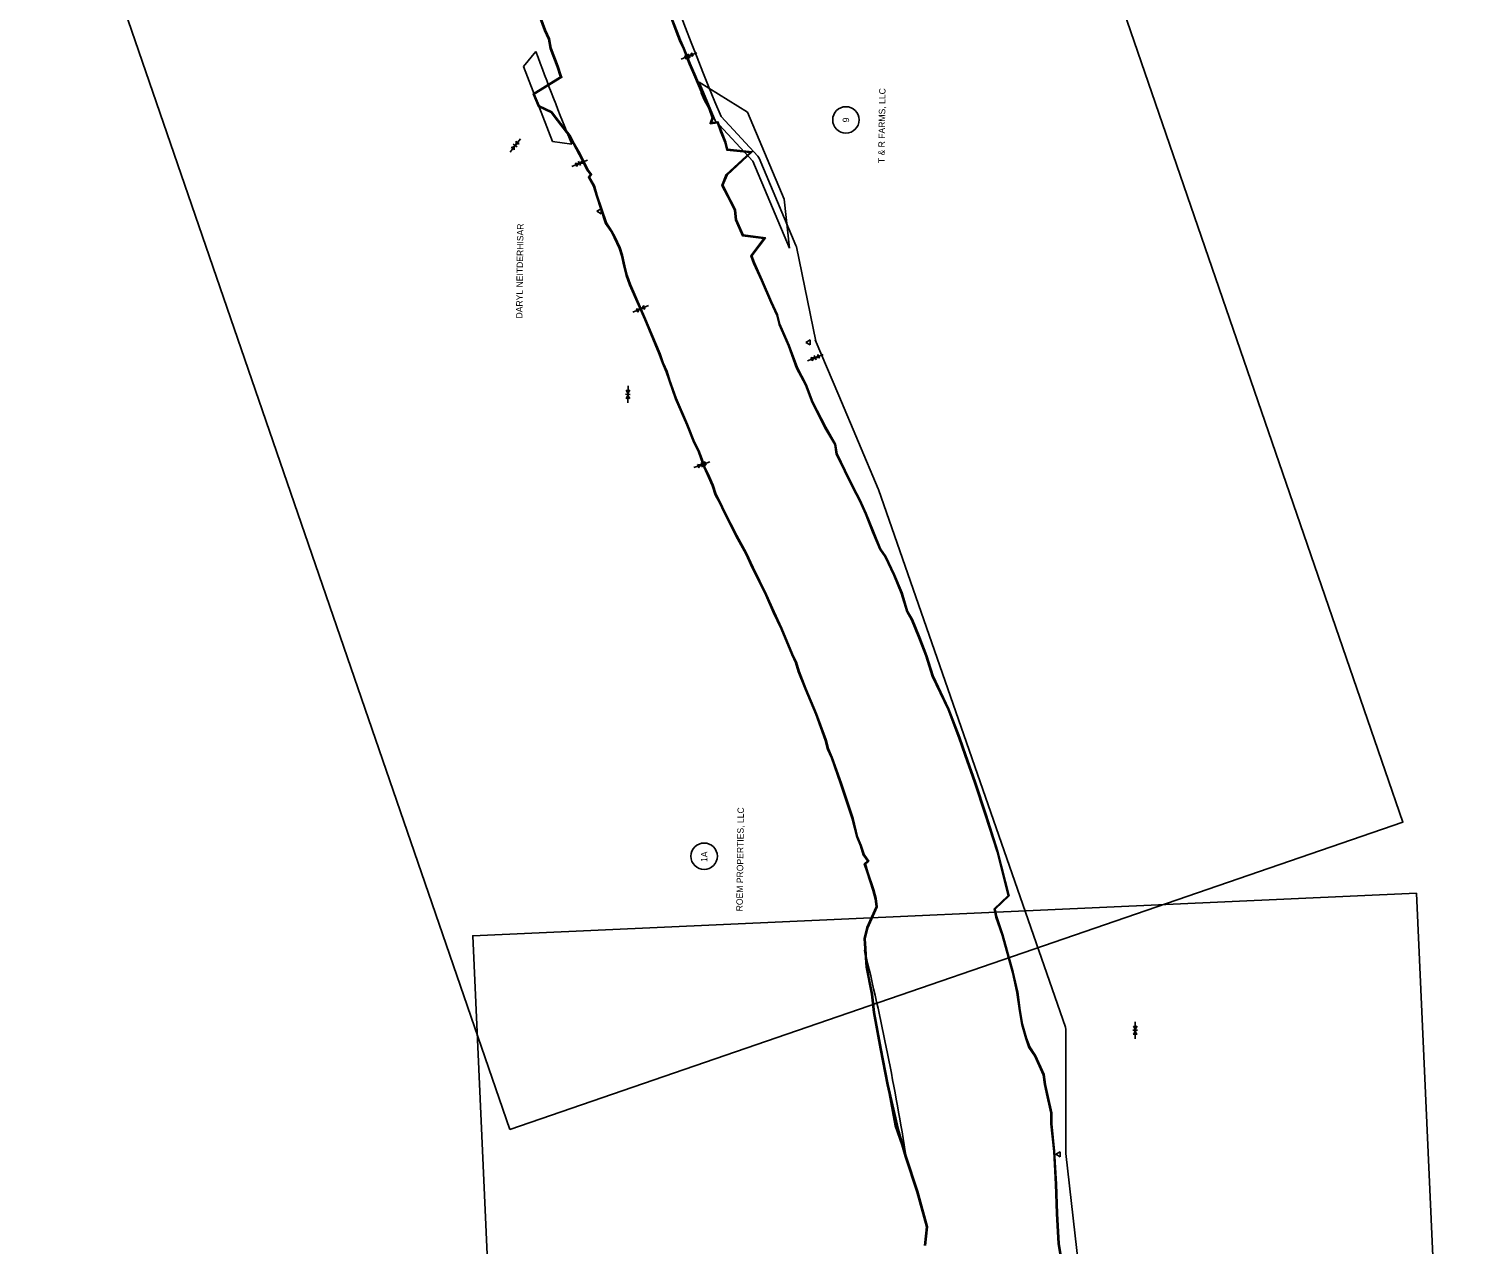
# Model space of a CAD drawing. Extents: x 20504422 to 20508365, y 7965199 to 7983597.
# Drawn here: x 20504612 to 20507690, y 7974062 to 7976636 of the extents above; entities that cross this region are included whole.
import ezdxf

# ---------------------------------------------------------------- set-up
doc = ezdxf.new("R2010")
doc.units = 0
for name, color, linetype in [('SurControl', 7, 'Continuous'), ('SurDikeDam', 7, 'Continuous'), ('SurLotCorner', 7, 'Continuous'), ('SurRipRap', 7, 'Continuous'), ('SurTopOfWater', 7, 'Continuous'), ('SurTreeLineRight', 7, 'Continuous'), ('SurWetlands', 7, 'Continuous')]:
    doc.layers.add(name, color=color, linetype=linetype)

msp = doc.modelspace()

# ---------------------------------------------------------------- linework, layer by layer
at = {"layer": 'SurControl'}
for centre in [(20506341.4, 7976443.5), (20506041.2, 7974884.6)]:
    msp.add_circle(centre, 28, dxfattribs=at)
at = {"layer": 'SurDikeDam'}
for p, q in [((20505658.9, 7976556.7), (20505684.8, 7976588.2)), ((20505720.3, 7976397.8), (20505658.9, 7976556.7)), ((20505760.7, 7976392), (20505720.3, 7976397.8)), ((20506406.5, 7974522.9), (20506380.8, 7974685.8)), ((20506406.5, 7974522.9), (20506380.8, 7974685.8)), ((20506445.8, 7974313.6), (20506406.5, 7974522.9)), ((20506445.8, 7974313.6), (20506406.5, 7974522.9)), ((20506469.3, 7974245.7), (20506445.8, 7974313.6)), ((20506469.3, 7974245.7), (20506445.8, 7974313.6))]:
    msp.add_line(p, q, dxfattribs=at)
msp.add_lwpolyline([(20506221.8, 7976172.1), (20506144.1, 7976356.4), (20506064.3, 7976442.5), (20506031, 7976523.2), (20506132.8, 7976460.2), (20506210.6, 7976275.9)], close=True, dxfattribs=at)
for centre, radius, start, end in [((20512535.1, 7979126.3), 7305.3, 200.33049, 201.9803), ((20500978.6, 7973370.7), 5560, 9.0549, 13.6819), ((20500978.6, 7973370.7), 5560, 9.0549, 13.6819)]:
    msp.add_arc(centre, radius, start, end, dxfattribs=at)
at = {"layer": 'SurLotCorner'}
for p, q in [((20506008.9, 7976578.9), (20505992.3, 7976572.1)), ((20506010.8, 7976574.2), (20506007, 7976583.5)), ((20506008.9, 7976578.9), (20506025.4, 7976585.6)), ((20505641.1, 7976389.3), (20505630.2, 7976375.2)), ((20505645.1, 7976386.2), (20505637.1, 7976392.4)), ((20505641.1, 7976389.3), (20505652.1, 7976403.4)), ((20505777.4, 7976351.7), (20505793.9, 7976358.4)), ((20505777.4, 7976351.7), (20505760.8, 7976344.9)), ((20505779.3, 7976347), (20505775.4, 7976356.4)), ((20505813.9, 7976250.2), (20505823.1, 7976255.3)), ((20505823, 7976244.8), (20505813.9, 7976250.2)), ((20505823.1, 7976255.3), (20505823, 7976244.8)), ((20505906.8, 7976043.4), (20505923.3, 7976050.3)), ((20505906.8, 7976043.4), (20505890.3, 7976036.4)), ((20505908.8, 7976038.7), (20505904.9, 7976048)), ((20506256.6, 7975972.5), (20506265.8, 7975977.6)), ((20506265.7, 7975967.1), (20506256.6, 7975972.5)), ((20506265.8, 7975977.6), (20506265.7, 7975967.1)), ((20506276.3, 7975940.1), (20506259.8, 7975933.3)), ((20506278.2, 7975935.4), (20506274.4, 7975944.8)), ((20506276.3, 7975940.1), (20506292.9, 7975946.9)), ((20505879.8, 7975862.5), (20505880, 7975880.4)), ((20505884.8, 7975862.5), (20505874.7, 7975862.6)), ((20505879.8, 7975862.5), (20505879.5, 7975844.7)), ((20506036.3, 7975713.4), (20506019.5, 7975707.3)), ((20506038, 7975708.6), (20506034.6, 7975718.1)), ((20506036.3, 7975713.4), (20506053.1, 7975719.4)), ((20506959, 7974516.1), (20506948.9, 7974516.3)), ((20506953.9, 7974516.2), (20506953.7, 7974498.3)), ((20506953.9, 7974516.2), (20506954.1, 7974534.1)), ((20506785.8, 7974253.6), (20506795, 7974258.7)), ((20506794.8, 7974248.2), (20506785.8, 7974253.6)), ((20506795, 7974258.7), (20506794.8, 7974248.2))]:
    msp.add_line(p, q, dxfattribs=at)
for centre, radius, start, end in [((20506004.8, 7976592.9), 14.6, 248.3327, 286.14), ((20505991.1, 7976571.6), 11.4, 1.639, 42.8526), ((20506015.8, 7976566), 14.6, 118.3517, 156.1589), ((20506001.9, 7976591.7), 14.6, 298.3517, 336.1589), ((20506012.9, 7976564.9), 14.6, 68.3327, 106.14), ((20506026.6, 7976586.1), 11.4, 181.639, 222.8526), ((20505630.7, 7976399.4), 14.6, 278.1957, 316.003), ((20505653.5, 7976381.6), 14.6, 148.2147, 186.0219), ((20505628.7, 7976397), 14.6, 328.2147, 6.0219), ((20505651.6, 7976379.1), 14.6, 98.1957, 136.003), ((20505652.9, 7976404.4), 11.4, 211.502, 252.7156), ((20505629.4, 7976374.1), 11.4, 31.502, 72.7156), ((20505770.4, 7976364.5), 14.6, 298.3517, 336.1589), ((20505795.1, 7976358.9), 11.4, 181.639, 222.8526), ((20505773.3, 7976365.7), 14.6, 248.3327, 286.14), ((20505759.6, 7976344.4), 11.4, 1.639, 42.8526), ((20505784.3, 7976338.8), 14.6, 118.3517, 156.1589), ((20505781.4, 7976337.7), 14.6, 68.3327, 106.14), ((20505899.8, 7976056.1), 14.6, 298.887, 336.6942), ((20505924.5, 7976050.8), 11.4, 182.1743, 223.3879), ((20505902.6, 7976057.3), 14.6, 248.868, 286.6753), ((20505889.1, 7976035.9), 11.4, 2.1743, 43.3879), ((20505913.9, 7976030.6), 14.6, 118.887, 156.6942), ((20505911, 7976029.4), 14.6, 68.868, 106.6753), ((20506272.3, 7975954.1), 14.6, 248.3327, 286.14), ((20506258.5, 7975932.8), 11.4, 1.639, 42.8526), ((20506283.2, 7975927.3), 14.6, 118.3517, 156.1589), ((20506269.4, 7975952.9), 14.6, 298.3517, 336.1589), ((20506280.4, 7975926.1), 14.6, 68.3327, 106.14), ((20506294.1, 7975947.4), 11.4, 181.639, 222.8526), ((20505865.2, 7975861.2), 14.6, 5.3849, 43.1922), ((20505880, 7975881.7), 11.4, 248.6722, 289.8859), ((20505894.3, 7975860.8), 14.6, 135.366, 173.1732), ((20505865.3, 7975864.3), 14.6, 315.366, 353.1732), ((20505879.5, 7975843.3), 11.4, 68.6722, 109.8859), ((20505894.3, 7975863.9), 14.6, 185.3849, 223.1922), ((20506032.9, 7975727.5), 14.6, 245.8008, 283.6081), ((20506018.2, 7975706.9), 11.4, 359.1071, 40.3208), ((20506042.6, 7975700.2), 14.6, 115.8198, 153.627), ((20506029.9, 7975726.5), 14.6, 295.8198, 333.627), ((20506039.7, 7975699.2), 14.6, 65.8008, 103.6081), ((20506054.4, 7975719.8), 11.4, 179.1071, 220.3208), ((20506939.4, 7974517.9), 14.6, 315.366, 353.1732), ((20506939.4, 7974514.8), 14.6, 5.3849, 43.1922), ((20506954.2, 7974535.4), 11.4, 248.6722, 289.8859), ((20506968.4, 7974514.5), 14.6, 135.366, 173.1732), ((20506968.4, 7974517.6), 14.6, 185.3849, 223.1922), ((20506953.7, 7974497), 11.4, 68.6722, 109.8859)]:
    msp.add_arc(centre, radius, start, end, dxfattribs=at)
at = {"layer": 'SurRipRap'}
for points in [[(20505629.6, 7974306.3), (20507520.7, 7974957.1), (20506503, 7977914.7), (20504611.9, 7977263.9)], [(20505692.1, 7971595), (20507690.1, 7971685.2), (20507549.3, 7974806.4), (20505551.3, 7974716.3)]]:
    msp.add_lwpolyline(points, close=True, dxfattribs=at)
at = {"layer": 'SurTopOfWater'}
for p, q in [((20505979.9, 7975857.9), (20505979.9, 7975857.9)), ((20506406.3, 7974523.4), (20506406.3, 7974523.4))]:
    msp.add_line(p, q, dxfattribs=at)
for points in [[(20505669.6, 7976725.4), (20505703.2, 7976632.5), (20505711.7, 7976614.6), (20505715.1, 7976594.7), (20505729.9, 7976555.9), (20505736.5, 7976536), (20505737.2, 7976534.7), (20505678.9, 7976498.7), (20505690.2, 7976471.6), (20505717.3, 7976459.2), (20505725.7, 7976448.1), (20505754.8, 7976410.3), (20505764.3, 7976392.6), (20505776.6, 7976370.5), (20505793.1, 7976337.6), (20505800.5, 7976327.9), (20505796.2, 7976322.2), (20505806.9, 7976303.2), (20505813.1, 7976282.6), (20505832.5, 7976224.5), (20505844.2, 7976207.1), (20505851, 7976194.3), (20505861.2, 7976172.1), (20505866.2, 7976156.4), (20505871.2, 7976133.9), (20505876.3, 7976113.9), (20505883.4, 7976094.6), (20505915.5, 7976021.1), (20505946.2, 7975947.6), (20505952.8, 7975928.5), (20505960.9, 7975910.3), (20505966.9, 7975891.5), (20505980.4, 7975853.3), (20506004.4, 7975798.2), (20506019.2, 7975760.8), (20506028.3, 7975743.1), (20506035, 7975724.7), (20506041.2, 7975707.3), (20506050.4, 7975687.1), (20506058.4, 7975669.2), (20506064.8, 7975650), (20506074.2, 7975631.8), (20506082.7, 7975613.7), (20506108.3, 7975562.8), (20506129.2, 7975525.1), (20506143.1, 7975495.2), (20506171.6, 7975437.3), (20506187.4, 7975401.5), (20506204.1, 7975366.2), (20506226.7, 7975312), (20506234.9, 7975294.6), (20506240.6, 7975276.1), (20506254.9, 7975239.3), (20506277.5, 7975185.1), (20506297.5, 7975130.4), (20506302.5, 7975111.1), (20506310.6, 7975092.9), (20506329.9, 7975037.7), (20506354.7, 7974963.7), (20506364.2, 7974925.4), (20506371.9, 7974907), (20506378.1, 7974887.6), (20506386.9, 7974874.8), (20506380.3, 7974868.9), (20506386.2, 7974850.2), (20506398.6, 7974813.1), (20506403.1, 7974794.8), (20506405.2, 7974777.5), (20506386, 7974733.8), (20506379.9, 7974710.2), (20506381.6, 7974689.5), (20506384, 7974649.7), (20506395.6, 7974592.4), (20506399.8, 7974553.7), (20506413.8, 7974477.1), (20506428.8, 7974400.8), (20506450.7, 7974305.9), (20506467, 7974249.3), (20506491.7, 7974174.4), (20506512.3, 7974100.1), (20506508.1, 7974060.8)], [(20505671.5, 7976726), (20505705, 7976633.3), (20505713.7, 7976615.2), (20505717.1, 7976595.2), (20505731.8, 7976556.6), (20505738.3, 7976536.8), (20505739.9, 7976534), (20505681.4, 7976497.8), (20505691.7, 7976473), (20505718.5, 7976460.9), (20505727.3, 7976449.3), (20505756.5, 7976411.4), (20505766.1, 7976393.5), (20505778.4, 7976371.5), (20505794.8, 7976338.6), (20505803, 7976327.9), (20505798.6, 7976322), (20505808.8, 7976304), (20505815, 7976283.2), (20505834.3, 7976225.4), (20505845.9, 7976208.1), (20505852.8, 7976195.2), (20505863.1, 7976172.9), (20505868.1, 7976156.9), (20505873.1, 7976134.4), (20505878.2, 7976114.5), (20505885.3, 7976095.3), (20505917.3, 7976021.9), (20505948.1, 7975948.3), (20505954.6, 7975929.3), (20505962.8, 7975911), (20505968.8, 7975892.1), (20505982.2, 7975854.1), (20506006.3, 7975799), (20506021, 7975761.6), (20506030.2, 7975743.9), (20506036.8, 7975725.3), (20506043, 7975708.1), (20506052.2, 7975688), (20506060.3, 7975669.9), (20506066.7, 7975650.8), (20506076, 7975632.7), (20506084.5, 7975614.6), (20506110.1, 7975563.7), (20506131, 7975526), (20506144.9, 7975496.1), (20506173.4, 7975438.1), (20506189.2, 7975402.4), (20506205.9, 7975367), (20506228.5, 7975312.8), (20506236.8, 7975295.3), (20506242.5, 7975276.7), (20506256.7, 7975240), (20506279.4, 7975185.8), (20506299.4, 7975131), (20506304.4, 7975111.8), (20506312.5, 7975093.6), (20506331.8, 7975038.4), (20506356.7, 7974964.3), (20506366.1, 7974926), (20506373.8, 7974907.6), (20506379.9, 7974888.4), (20506389.6, 7974874.4), (20506382.6, 7974868.3), (20506388.1, 7974850.8), (20506400.5, 7974813.7), (20506405.1, 7974795.2), (20506407.2, 7974777.2), (20506387.9, 7974733.2), (20506381.9, 7974710), (20506383.6, 7974689.6), (20506386, 7974650), (20506397.6, 7974592.7), (20506401.8, 7974554), (20506415.8, 7974477.5), (20506430.8, 7974401.3), (20506452.6, 7974306.4), (20506468.9, 7974249.9), (20506493.6, 7974175), (20506514.4, 7974100.3), (20506510.1, 7974060.8)], [(20505968.2, 7976666.1), (20505982.1, 7976629.7), (20505989.3, 7976611.7), (20505997.4, 7976593.9), (20506009.8, 7976562.2), (20506019.3, 7976539.6), (20506034.8, 7976502.9), (20506035, 7976500.7), (20506041.5, 7976485.7), (20506050.8, 7976468.3), (20506058.4, 7976447.9), (20506053.9, 7976436.1), (20506054.2, 7976435.5), (20506069.2, 7976437.4), (20506076.1, 7976418.9), (20506085.1, 7976396.1), (20506089.2, 7976379.6), (20506138.3, 7976374.7), (20506088, 7976328), (20506078.5, 7976305), (20506096.1, 7976271.4), (20506105.7, 7976252.7), (20506107.9, 7976231.8), (20506122.3, 7976198.4), (20506167.5, 7976192.6), (20506139.7, 7976156), (20506145.9, 7976140.1), (20506162.3, 7976103.7), (20506182.2, 7976057.8), (20506194.9, 7976030.2), (20506199.7, 7976010.4), (20506219.6, 7975964.9), (20506236.8, 7975918), (20506255.7, 7975882.6), (20506269.8, 7975845.2), (20506279, 7975827.6), (20506296.8, 7975791.8), (20506317.7, 7975756.3), (20506320.6, 7975735.7), (20506338.2, 7975700.6), (20506355.9, 7975664.7), (20506370, 7975637.8), (20506382.5, 7975609.6), (20506397.7, 7975571.7), (20506413, 7975534.5), (20506424.4, 7975518.4), (20506442.6, 7975479.9), (20506458.6, 7975441.8), (20506470.2, 7975402.9), (20506480.5, 7975385.1), (20506495.7, 7975346.8), (20506510.8, 7975308.6), (20506524.1, 7975266), (20506557.6, 7975195.2), (20506580.5, 7975135.2), (20506593.2, 7975098.7), (20506613.6, 7975040.6), (20506636.2, 7974972.3), (20506661.3, 7974894), (20506685, 7974801.6), (20506655.3, 7974773), (20506658.7, 7974756), (20506671.9, 7974717.4), (20506693.8, 7974638.4), (20506703.6, 7974596.4), (20506708.6, 7974557.6), (20506713.6, 7974528.4), (20506722, 7974498.7), (20506729, 7974480), (20506741.3, 7974461.7), (20506759, 7974422.2), (20506761.7, 7974401.4), (20506766.3, 7974381.6), (20506775.1, 7974341), (20506775.4, 7974317.9), (20506781.3, 7974259.7), (20506784.9, 7974190.4), (20506787.3, 7974128.3), (20506791, 7974064.3), (20506795.7, 7974034.3)], [(20505970.1, 7976666.8), (20505984, 7976630.4), (20505991.1, 7976612.5), (20505999.2, 7976594.7), (20506011.6, 7976563), (20506021.2, 7976540.4), (20506036.8, 7976503.4), (20506037, 7976501.1), (20506043.3, 7976486.6), (20506052.7, 7976469.1), (20506060.5, 7976447.9), (20506056.7, 7976437.9), (20506070.5, 7976439.5), (20506078, 7976419.6), (20506087, 7976396.7), (20506090.8, 7976381.4), (20506142.9, 7976376.2), (20506089.7, 7976326.9), (20506080.7, 7976305.1), (20506097.9, 7976272.4), (20506107.6, 7976253.3), (20506109.8, 7976232.3), (20506123.7, 7976200.2), (20506171.1, 7976194.1), (20506142, 7976155.7), (20506147.8, 7976140.8), (20506164.1, 7976104.5), (20506184.1, 7976058.7), (20506196.8, 7976030.8), (20506201.6, 7976011.1), (20506221.5, 7975965.6), (20506238.6, 7975918.9), (20506257.5, 7975883.5), (20506271.6, 7975846), (20506280.8, 7975828.5), (20506298.6, 7975792.8), (20506319.6, 7975757), (20506322.5, 7975736.3), (20506340, 7975701.5), (20506357.7, 7975665.6), (20506371.8, 7975638.7), (20506384.3, 7975610.4), (20506399.5, 7975572.4), (20506414.8, 7975535.5), (20506426.1, 7975519.4), (20506444.4, 7975480.7), (20506460.4, 7975442.5), (20506472, 7975403.7), (20506482.3, 7975386), (20506497.6, 7975347.5), (20506512.7, 7975309.2), (20506525.9, 7975266.8), (20506559.4, 7975195.9), (20506582.4, 7975135.9), (20506595.1, 7975099.3), (20506615.5, 7975041.2), (20506638.1, 7974973), (20506663.3, 7974894.5), (20506687.2, 7974801), (20506657.4, 7974772.3), (20506660.6, 7974756.5), (20506673.8, 7974718), (20506695.8, 7974638.9), (20506705.6, 7974596.8), (20506710.5, 7974557.9), (20506715.6, 7974528.9), (20506723.9, 7974499.3), (20506730.8, 7974480.9), (20506743, 7974462.7), (20506761, 7974422.7), (20506763.7, 7974401.7), (20506768.2, 7974382), (20506777.1, 7974341.2), (20506777.4, 7974318), (20506783.3, 7974259.9), (20506786.9, 7974190.4), (20506789.3, 7974128.4), (20506793, 7974064.5), (20506797.7, 7974034.6)]]:
    msp.add_lwpolyline(points, dxfattribs=at)
at = {"layer": 'SurTreeLineRight'}
msp.add_lwpolyline([(20506903.5, 7973403.1), (20506806.8, 7974255.2), (20506806.9, 7974253.5), (20506807.3, 7974517.6), (20506806.4, 7974522.6), (20506410.1, 7975661.4), (20506409.8, 7975662.3), (20506326.3, 7975860.1), (20506276.5, 7975978.2), (20506277.4, 7975975.4), (20506236.5, 7976175.1), (20506235.6, 7976177.9), (20506157.9, 7976362.2), (20506155.1, 7976366.6), (20506077.1, 7976450.7)], dxfattribs=at)
msp.add_arc((20511205.4, 7978611.7), 5565, 180.6542, 202.8501, dxfattribs=at)
at = {"layer": 'SurWetlands'}
for p, q in [((20505658.9, 7976556.7), (20505684.8, 7976588.2)), ((20505720.3, 7976397.8), (20505658.9, 7976556.7)), ((20506031, 7976523.2), (20506132.8, 7976460.2)), ((20506132.8, 7976460.2), (20506210.6, 7976275.9)), ((20505760.7, 7976392), (20505720.3, 7976397.8)), ((20506210.6, 7976275.9), (20506221.8, 7976172.1)), ((20506406.5, 7974522.9), (20506380.8, 7974685.8)), ((20506445.8, 7974313.6), (20506406.5, 7974522.9)), ((20506469.3, 7974245.7), (20506445.8, 7974313.6))]:
    msp.add_line(p, q, dxfattribs=at)

# ---------------------------------------------------------------- texts
at = {"layer": 'SurControl'}
for s, p in [('T & R FARMS, LLC', (20506423.3, 7976352)), ('9', (20506348.1, 7976438.3)), ('DARYL NEITDERHISAR', (20505656.4, 7976023)), ('ROEM PROPERTIES, LLC', (20506122.8, 7974767.9)), ('1A', (20506047.9, 7974872.4))]:
    msp.add_text(s, height=13.6, rotation=89.2974, dxfattribs=at).set_placement(p)

doc.saveas('drawing.dxf')
